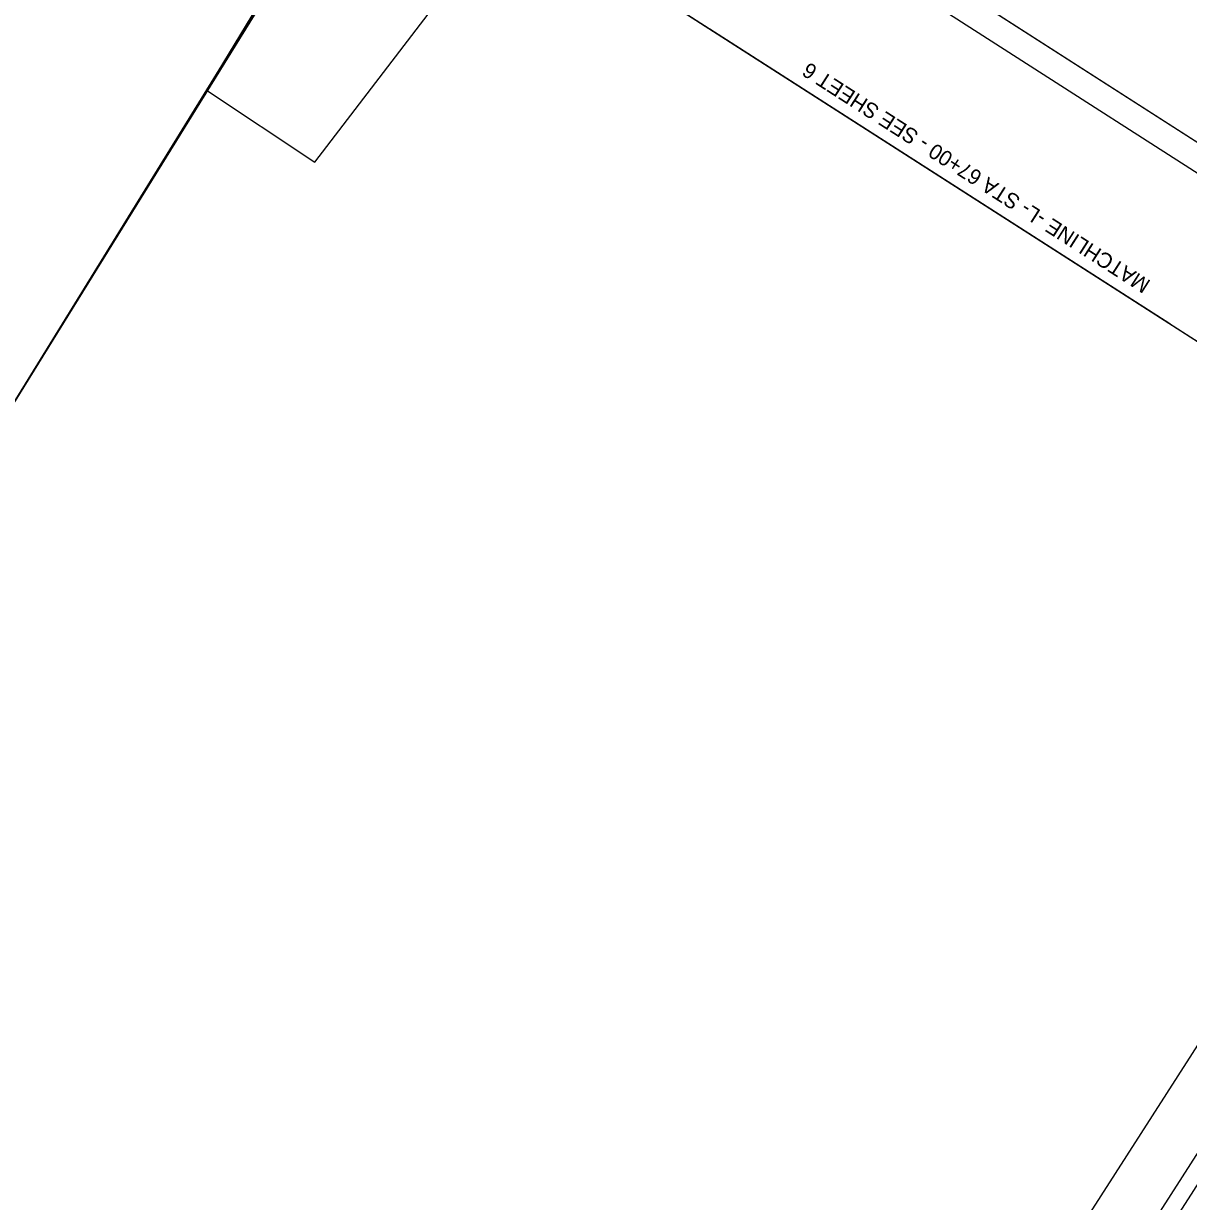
# Model space of a CAD drawing. Extents: x 2346049 to 2349719, y 842061 to 846435.
# Drawn here: x 2347884 to 2349027, y 844432 to 845588 of the extents above; entities that cross this region are included whole.
import ezdxf

# ---------------------------------------------------------------- set-up
doc = ezdxf.new("R2010")
doc.units = 0
for name, color, linetype in [('Matchline', 7, 'Continuous'), ('Matchline Text', 7, 'Continuous'), ('Scratch_Level_0', 7, 'Continuous'), ('Sheet Detail CELL', 7, 'Continuous'), ('Sheet Plot Border Inside CELL', 7, 'Continuous'), ('Sheet Plot Border Outside CELL', 7, 'Continuous')]:
    doc.layers.add(name, color=color, linetype=linetype)

msp = doc.modelspace()

# ---------------------------------------------------------------- linework, layer by layer
at = {"layer": 'Matchline'}
msp.add_line((2348557.5, 845583.3), (2349009, 845293.7), dxfattribs=at)
at = {"layer": 'Scratch_Level_0'}
for points in [[(2347005, 844312.5), (2347188.2, 844598.2), (2347979.3, 845831.9), (2348174.5, 845706.7), (2348063.3, 845523.1), (2348169.5, 845452.2), (2348364.5, 845707), (2348364.5, 845707), (2348364.5, 845707), (2349350.4, 845074.8), (2349350.4, 845074.8), (2349350.4, 845074.8), (2348851.8, 844297.2)], [(2347005, 844312.5), (2347188.2, 844598.2), (2347979.3, 845831.9), (2348174.5, 845706.7), (2348235.6, 845791.3), (2348313, 845745.3), (2348364.5, 845707), (2348364.5, 845707), (2348364.5, 845707), (2349350.4, 845074.8), (2349350.4, 845074.8), (2349350.4, 845074.8), (2348851.8, 844297.2)], [(2347188.2, 844598.2), (2347405.1, 844503.5), (2347561.1, 844746.9), (2347567.3, 844745.9), (2347677, 844903.8), (2347773, 845052.5), (2348176, 845705.7), (2347979.3, 845831.9), (2347188.2, 844598.2)], [(2346937.8, 844263.6), (2347160.2, 844610.4), (2347405.1, 844503.5), (2347561.1, 844746.9), (2347567.3, 844745.9), (2347677, 844903.8), (2347773, 845052.5), (2348231.5, 845792.3), (2348231.5, 845792.3), (2348231.5, 845792.3), (2349350.4, 845074.8), (2349350.4, 845074.8), (2349350.4, 845074.8), (2348851.8, 844297.2)]]:
    msp.add_lwpolyline(points, dxfattribs=at)
msp.add_lwpolyline([(2347188.2, 844598.2), (2347405.1, 844503.5), (2347561.1, 844746.9), (2347567.3, 844745.9), (2347677, 844903.8), (2347773, 845052.5), (2348176, 845705.7), (2347979.3, 845831.9)], close=True, dxfattribs=at)
at = {"layer": 'Sheet Detail CELL'}
msp.add_lwpolyline([(2346465.3, 843526.7), (2348084.7, 846052), (2349473.7, 845161.3), (2347854.2, 842636)], close=True, dxfattribs=at)
at = {"layer": 'Sheet Plot Border Inside CELL'}
msp.add_lwpolyline([(2348083.9, 846082.3), (2346302.5, 843304.4), (2347720, 842395.3), (2349501.5, 845173.2)], close=True, dxfattribs=at)
at = {"layer": 'Sheet Plot Border Outside CELL'}
msp.add_lwpolyline([(2347866.8, 846221.5), (2346048.7, 843386.4), (2347900.5, 842198.8), (2349718.7, 845033.9)], close=True, dxfattribs=at)

# ---------------------------------------------------------------- texts
at = {"layer": 'Matchline Text'}
msp.add_text('MATCHLINE -L- STA 67+00 - SEE SHEET 6', height=15, rotation=147.3281, dxfattribs=at).set_placement((2348991.2, 845335.3))

doc.saveas('drawing.dxf')
